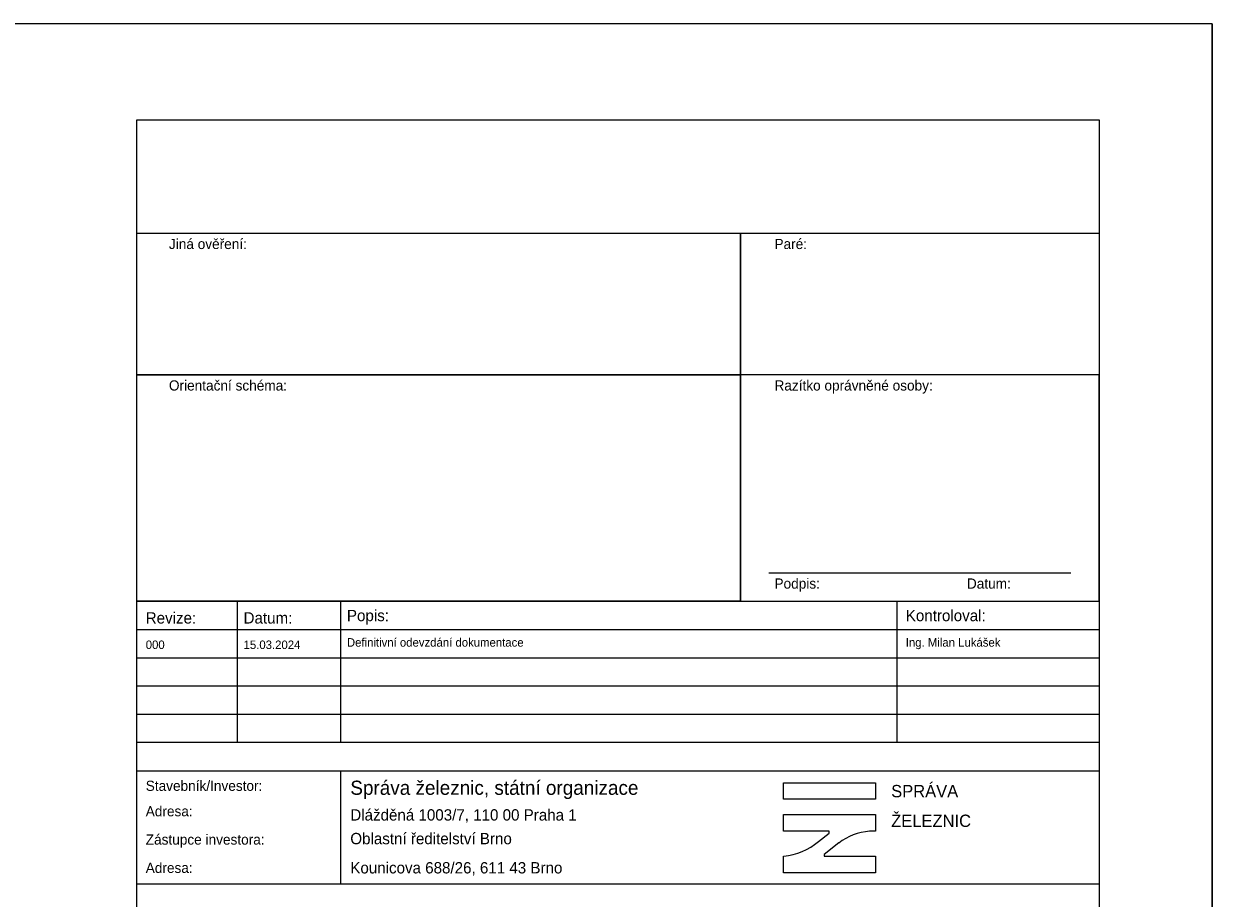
# Model space of a CAD drawing. Extents: x 2343 to 7744, y -6590 to 2050.
# Drawn here: x 5840 to 6050, y -6447.5 to -6293 of the extents above; entities that cross this region are included whole.
import ezdxf

# ---------------------------------------------------------------- set-up
doc = ezdxf.new("R2010")
doc.units = 0
for name, color, linetype in [('Default', 7, 'Continuous'), ('Rozpiska_Logo', 7, 'Continuous'), ('Rozpiska_pola_3', 7, 'Continuous'), ('Rozpiska_pole_1', 7, 'Continuous'), ('Rozpiska_pole_2', 7, 'Continuous'), ('Rozpiska_pole_4', 7, 'Continuous'), ('Rozpiska_pole_5', 7, 'Continuous'), ('Rozpiska_pole_6', 7, 'Continuous'), ('Vrstva 63', 7, 'Continuous')]:
    doc.layers.add(name, color=color, linetype=linetype)

msp = doc.modelspace()

# ---------------------------------------------------------------- linework, layer by layer
at = {"layer": 'Default'}
for p, q in [((6050, -6293), (6050, -6590)), ((5966.65, -6395), (5966.65, -6330))]:
    msp.add_line(p, q, dxfattribs=at)
at = {"layer": 'Rozpiska_Logo'}
for p, q in [((5980.4, -6437.47), (5982.34, -6436.01)), ((5982.34, -6436.01), (5982.34, -6435.66)), ((5984.03, -6437.74), (5981.42, -6439.76)), ((5981.42, -6439.76), (5981.42, -6440.07))]:
    msp.add_line(p, q, dxfattribs=at)
msp.add_lwpolyline([(5974.22, -6427.09), (5990.52, -6427.09), (5990.52, -6430.02), (5974.22, -6430.02)], close=True, dxfattribs=at)
for points in [[(5982.34, -6435.66), (5974.22, -6435.66), (5974.22, -6432.73), (5990.52, -6432.73), (5990.52, -6435.66), (5989.44, -6435.66)], [(5981.42, -6440.07), (5990.52, -6440.07), (5990.52, -6443), (5974.22, -6443), (5974.22, -6440.07), (5974.28, -6440.07)]]:
    msp.add_lwpolyline(points, dxfattribs=at)
for centre, radius, start, end in [((5990.18, -6445.68), 10.04, 94.2142, 127.7808), ((5973.44, -6429.58), 10.52, 274.6014, 311.4254)]:
    msp.add_arc(centre, radius, start, end, dxfattribs=at)
at = {"layer": 'Rozpiska_pola_3'}
msp.add_line((5971.65, -6390), (6025, -6390), dxfattribs=at)
at = {"layer": 'Rozpiska_pole_1'}
msp.add_lwpolyline([(5860, -6310), (6030, -6310), (6030, -6575), (5860, -6575)], close=True, dxfattribs=at)
at = {"layer": 'Rozpiska_pole_2'}
for points in [[(5860, -6330), (5966.65, -6330), (5966.65, -6355), (5860, -6355)], [(5966.65, -6330), (6030, -6330), (6030, -6355), (5966.65, -6355)], [(5860, -6355), (5966.65, -6355), (5966.65, -6395), (5860, -6395)], [(6030, -6355), (5966.65, -6355), (5966.65, -6395), (6030, -6395)]]:
    msp.add_lwpolyline(points, close=True, dxfattribs=at)
at = {"layer": 'Rozpiska_pole_4'}
for p, q in [((5877.78, -6420), (5877.78, -6395)), ((5896.05, -6420), (5896.05, -6395)), ((5994.3, -6420), (5994.3, -6395)), ((5860, -6400), (6030, -6400)), ((5860, -6405), (6030, -6405)), ((5860, -6410), (6030, -6410)), ((5860, -6415), (6030, -6415))]:
    msp.add_line(p, q, dxfattribs=at)
msp.add_lwpolyline([(5860, -6395), (6030, -6395), (6030, -6420), (5860, -6420)], close=True, dxfattribs=at)
at = {"layer": 'Rozpiska_pole_5'}
msp.add_line((5896.05, -6445), (5896.05, -6425), dxfattribs=at)
msp.add_lwpolyline([(5860, -6425), (6030, -6425), (6030, -6445), (5860, -6445)], close=True, dxfattribs=at)
at = {"layer": 'Vrstva 63'}
msp.add_lwpolyline([(5630, -6590), (6050, -6590), (6050, -6293), (5630, -6293)], close=True, dxfattribs=at)

# ---------------------------------------------------------------- texts
at = {"layer": 'Rozpiska_pola_3'}
for s, p in [('Paré:', (5972.65, -6332.8)), ('Razítko oprávněné osoby:', (5972.65, -6357.8)), ('Podpis:', (5972.65, -6392.8)), ('Datum:', (6006.65, -6392.8))]:
    msp.add_text(s, height=1.8, dxfattribs=at).set_placement(p)
at = {"layer": 'Rozpiska_pole_2'}
for s, p in [('Jiná ověření:', (5865.65, -6332.8)), ('Orientační schéma:', (5865.65, -6357.8))]:
    msp.add_text(s, height=1.8, dxfattribs=at).set_placement(p)
at = {"layer": 'Rozpiska_pole_4'}
for s, height, p in [('Popis:', 2, (5897.1, -6398.55)), ('Kontroloval:', 2, (5995.85, -6398.55)), ('Revize:', 2, (5861.55, -6398.97)), ('Datum:', 2, (5878.84, -6398.97)), ('000', 1.5, (5861.55, -6403.47)), ('15.03.2024', 1.5, (5878.84, -6403.47)), ('Definitivní odevzdání dokumentace', 1.5, (5897.1, -6403.05)), ('Ing. Milan Lukášek', 1.5, (5995.85, -6403.05))]:
    msp.add_text(s, height=height, dxfattribs=at).set_placement(p)
at = {"layer": 'Rozpiska_pole_5'}
for s, height, p in [('Stavebník/Investor:', 1.8, (5861.55, -6428.53)), ('Správa železnic, státní organizace', 2.5, (5897.7, -6429.23)), ('Adresa:', 1.8, (5861.55, -6433.03)), ('Zástupce investora:', 1.8, (5861.55, -6438.03)), ('Adresa:', 1.8, (5861.55, -6443.03))]:
    msp.add_text(s, height=height, dxfattribs=at).set_placement(p)
at = {"layer": 'Rozpiska_pole_6'}
for s, height, p in [('SPRÁVA', 2.183, (5993.27, -6429.67)), ('Dlážděná 1003/7, 110 00 Praha 1', 2, (5897.7, -6433.78)), ('ŽELEZNIC', 2.183, (5993.27, -6434.91)), ('Oblastní ředitelství Brno', 2, (5897.7, -6437.96)), ('Kounicova 688/26, 611 43 Brno', 2, (5897.7, -6443.12))]:
    msp.add_text(s, height=height, dxfattribs=at).set_placement(p)

doc.saveas('drawing.dxf')
